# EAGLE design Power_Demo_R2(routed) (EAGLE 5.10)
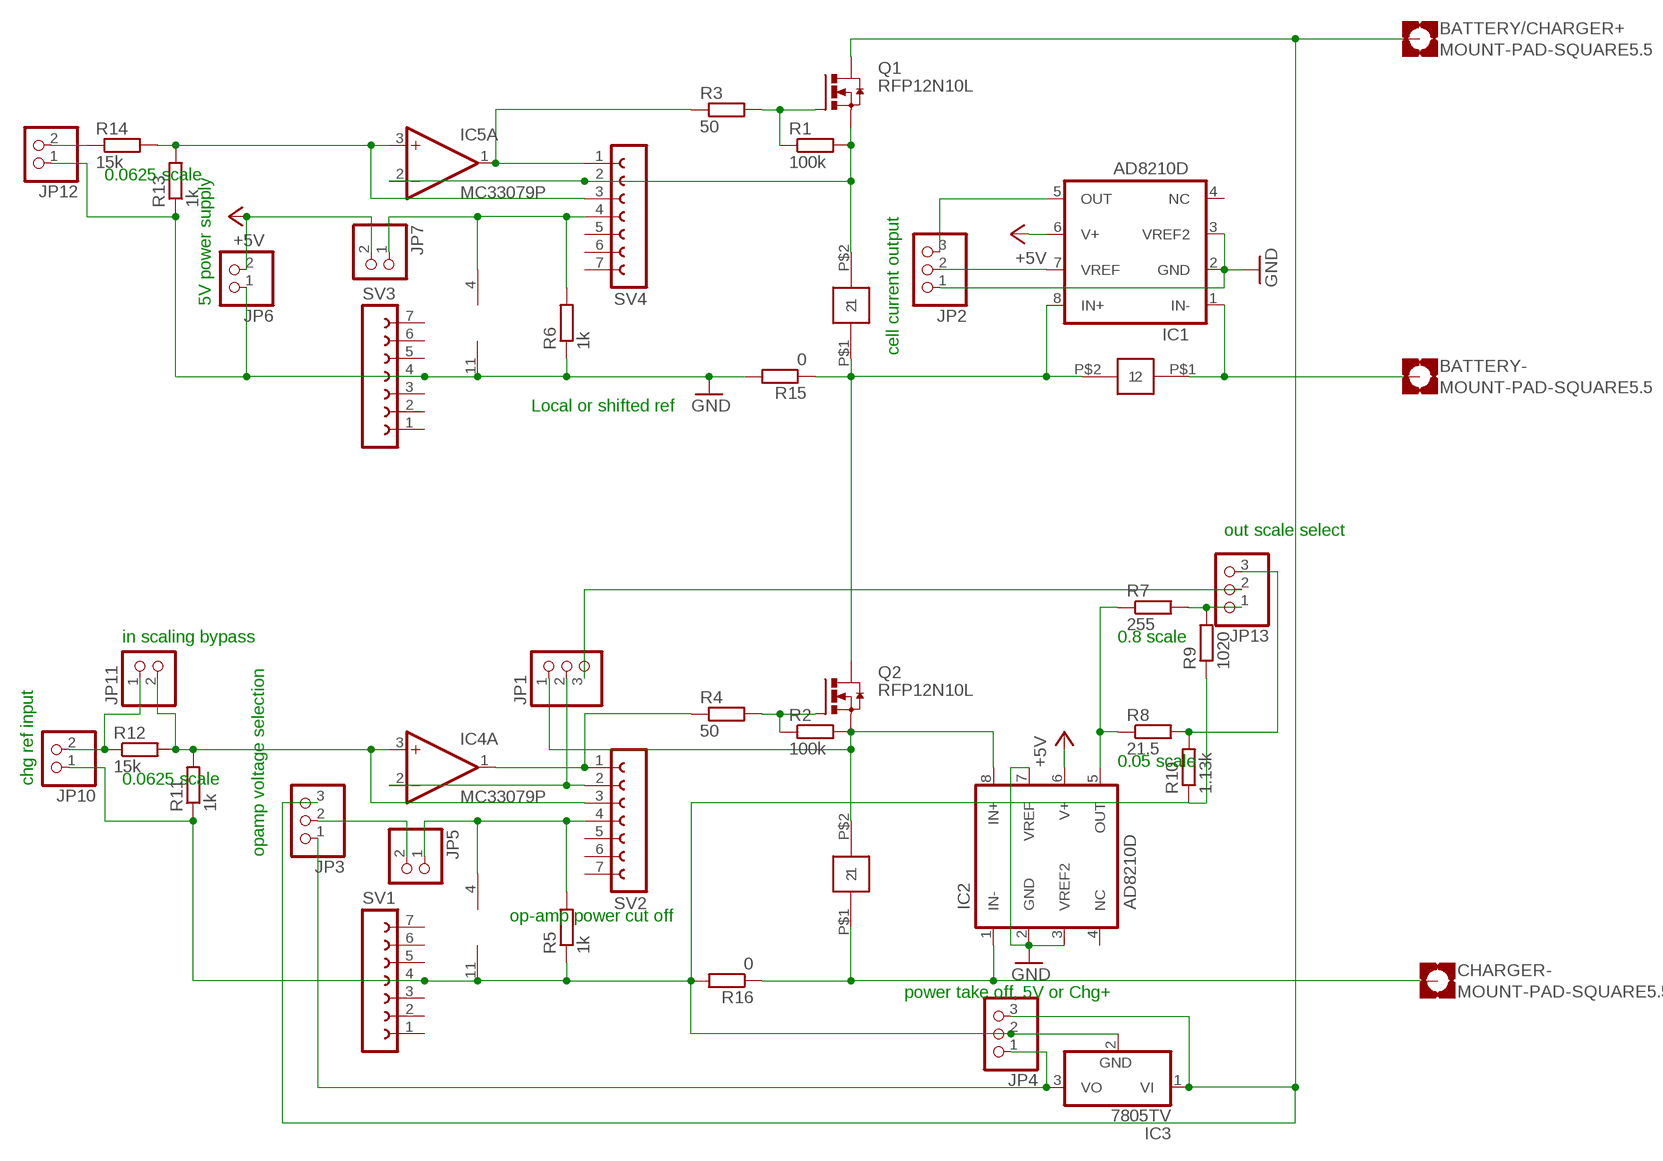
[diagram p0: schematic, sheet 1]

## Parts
BATTERY-  MOUNT-PAD-SQUARE5.5  [5,5-PAD-SQUARE]
BATTERY/CHARGER+  MOUNT-PAD-SQUARE5.5  [5,5-PAD-SQUARE]
CHARGER-  MOUNT-PAD-SQUARE5.5  [5,5-PAD-SQUARE]
IC1  AD8210D  [SO08]
IC2  AD8210D  [SO08]
IC3  7805TV  [TO220V]
IC4  MC33079P  [DIL14]
IC5  MC33079P  [DIL14]
JP1  PINHD-1X3  [1X03]
JP2  PINHD-1X3  [1X03]
JP3  PINHD-1X3  [1X03]
JP4  PINHD-1X3  [1X03]
JP5  PINHD-1X2  [1X02]
JP6  PINHD-1X2  [1X02]
JP7  PINHD-1X2  [1X02]
JP10  PINHD-1X2  [1X02]
JP11  PINHD-1X2  [1X02]
JP12  PINHD-1X2  [1X02]
JP13  PINHD-1X3  [1X03]
Q1  RFP12N10L  [TO220-W/657-20ABP]
Q2  RFP12N10L  [TO220-W/657-20ABP]
R1  100k  R-EU_R0805  [R0805]
R2  100k  R-EU_R0805  [R0805]
R3  50  R-EU_R0805  [R0805]
R4  50  R-EU_R0805  [R0805]
R5  1k  R-EU_R0805  [R0805]
R6  1k  R-EU_R0805  [R0805]
R7  255  R-EU_R0805  [R0805]
R8  21.5  R-EU_R0805  [R0805]
R9  1020  R-EU_R0805  [R0805]
R10  1.13k  R-EU_R0805  [R0805]
R11  1k  R-EU_R0805  [R0805]
R12  15k  R-EU_R0805  [R0805]
R13  1k  R-EU_R0805  [R0805]
R14  15k  R-EU_R0805  [R0805]
R15  0  R-EU_R0805  [R0805]
R16  0  R-EU_R0805  [R0805]
SV1  FE07-1  [FE07]
SV2  FE07-1  [FE07]
SV3  FE07-1  [FE07]
SV4  FE07-1  [FE07]
U$1  630HR050E  [630HR050E]
U$2  630HR050E  [630HR050E]
U$3  630HR050E  [630HR050E]

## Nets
+5V: IC1.6(V+) IC2.6(V+) JP6.2 JP7.2
GND: IC1.2(GND) IC1.3(VREF2) IC2.2(GND) IC2.3(VREF2) IC2.7(VREF) IC5.11(P:V-) JP2.1 JP6.1 JP12.1 R6.1 R13.1 R15.2 SV3.4
LOAD: BATTERY/CHARGER+.B5,5(MOUNT) IC3.1(VI) JP3.3 JP4.3 Q1.2(D)
N$1: IC1.8(IN+) Q2.2(D) R15.1 U$1.P$1 U$2.P$2
N$2: IC3.3(VO) JP3.1 JP4.1
N$3: IC2.8(IN+) JP1.1 Q2.3(S) R2.2 U$3.P$2
N$4: IC1.5(OUT) JP2.3
N$5: BATTERY-.B5,5(MOUNT) IC1.1(IN-) U$2.P$1
N$6: Q2.1(G) R2.1 R4.2
N$8: Q1.1(G) R1.1 R3.2
N$9: IC1.7(VREF) JP2.2
N$10: JP1.3 JP13.2
N$11: CHARGER-.B5,5(MOUNT) IC2.1(IN-) R16.1 U$3.P$1
N$12: IC4.4(P:V+) JP5.1 R5.2 SV2.4
N$13: IC4.1(A:OUT) R4.1 SV2.1
N$14: IC4.2(A:-IN) JP1.2 SV2.2
N$15: JP13.1 R7.2 R9.2
N$17: JP10.2 JP11.1 R12.1
N$18: JP3.2 JP5.2
N$19: IC4.3(A:+IN) JP11.2 R11.2 R12.2 SV2.3
N$20: IC5.1(A:OUT) R3.1 SV4.1
N$21: IC5.2(A:-IN) Q1.3(S) R1.2 SV4.2 U$1.P$2
N$22: IC2.5(OUT) R7.1 R8.1
N$23: JP13.3 R8.2 R10.2
N$24: IC5.4(P:V+) JP7.1 R6.2 SV4.4
N$27: JP12.2 R14.1
N$28: IC5.3(A:+IN) R13.2 R14.2 SV4.3
N$29: IC3.2(GND) IC4.11(P:V-) JP4.2 JP10.1 R5.1 R9.1 R10.1 R11.1 R16.2 SV1.4
Unconnected: IC4.5(B:+IN) IC4.6(B:-IN) IC4.7(B:OUT) IC4.8(C:OUT) IC4.9(C:-IN) IC4.10(C:+IN) IC4.12(D:+IN) IC4.13(D:-IN) IC4.14(D:OUT) IC5.5(B:+IN) IC5.6(B:-IN) IC5.7(B:OUT) IC5.8(C:OUT) IC5.9(C:-IN) IC5.10(C:+IN) IC5.12(D:+IN) IC5.13(D:-IN) IC5.14(D:OUT) SV1.1 SV1.2 SV1.3 SV1.5 SV1.6 SV1.7 SV2.5 SV2.6 SV2.7 SV3.1 SV3.2 SV3.3 SV3.5 SV3.6 SV3.7 SV4.5 SV4.6 SV4.7

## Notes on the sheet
- 0.0625 scale
- cell current output
- 5V power supply
- Local or shifted ref
- out scale select
- in scaling bypass | 0.8 scale
- 0.05 scale
- chg ref input | 0.0625 scale
- opamp voltage selection
- op-amp power cut off
- power take off, 5V or Chg+

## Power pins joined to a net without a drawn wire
NC: IC1.4(NC) IC2.4(NC)

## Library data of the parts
BATTERY- BATTERY/CHARGER+ CHARGER- = holes:MOUNT-PAD-SQUARE: MOUNTING PAD, square
IC1 IC2 = NEWPARTS:AD8210: High Voltage, Bidirectional Current Shunt Monitor
IC3 = linear:78*: Positive VOLTAGE REGULATOR Source: http://cache.national.com/ds/LM/LM78L05.pdf http://www.fairchildsemi.com/ds/LM/LM7805.pdf
IC4 IC5 = linear:MC33079: OP AMP
JP1-JP4 JP13 = pinhead:PINHD-1X3: PIN HEADER
JP5-JP7 JP10-JP12 = pinhead:PINHD-1X2: PIN HEADER
Q1 Q2 = NEWPARTS:RFP12N10L: N-Channel Power MOSFET 100V; 12A; 0,2Ohm< Logic Level
R1-R16 = rcl:R-EU_: RESISTOR, European symbol
SV1-SV4 = con-lsta:FE07-1: FEMALE HEADER
U$1-U$3 = NEWPARTS:630HR050E

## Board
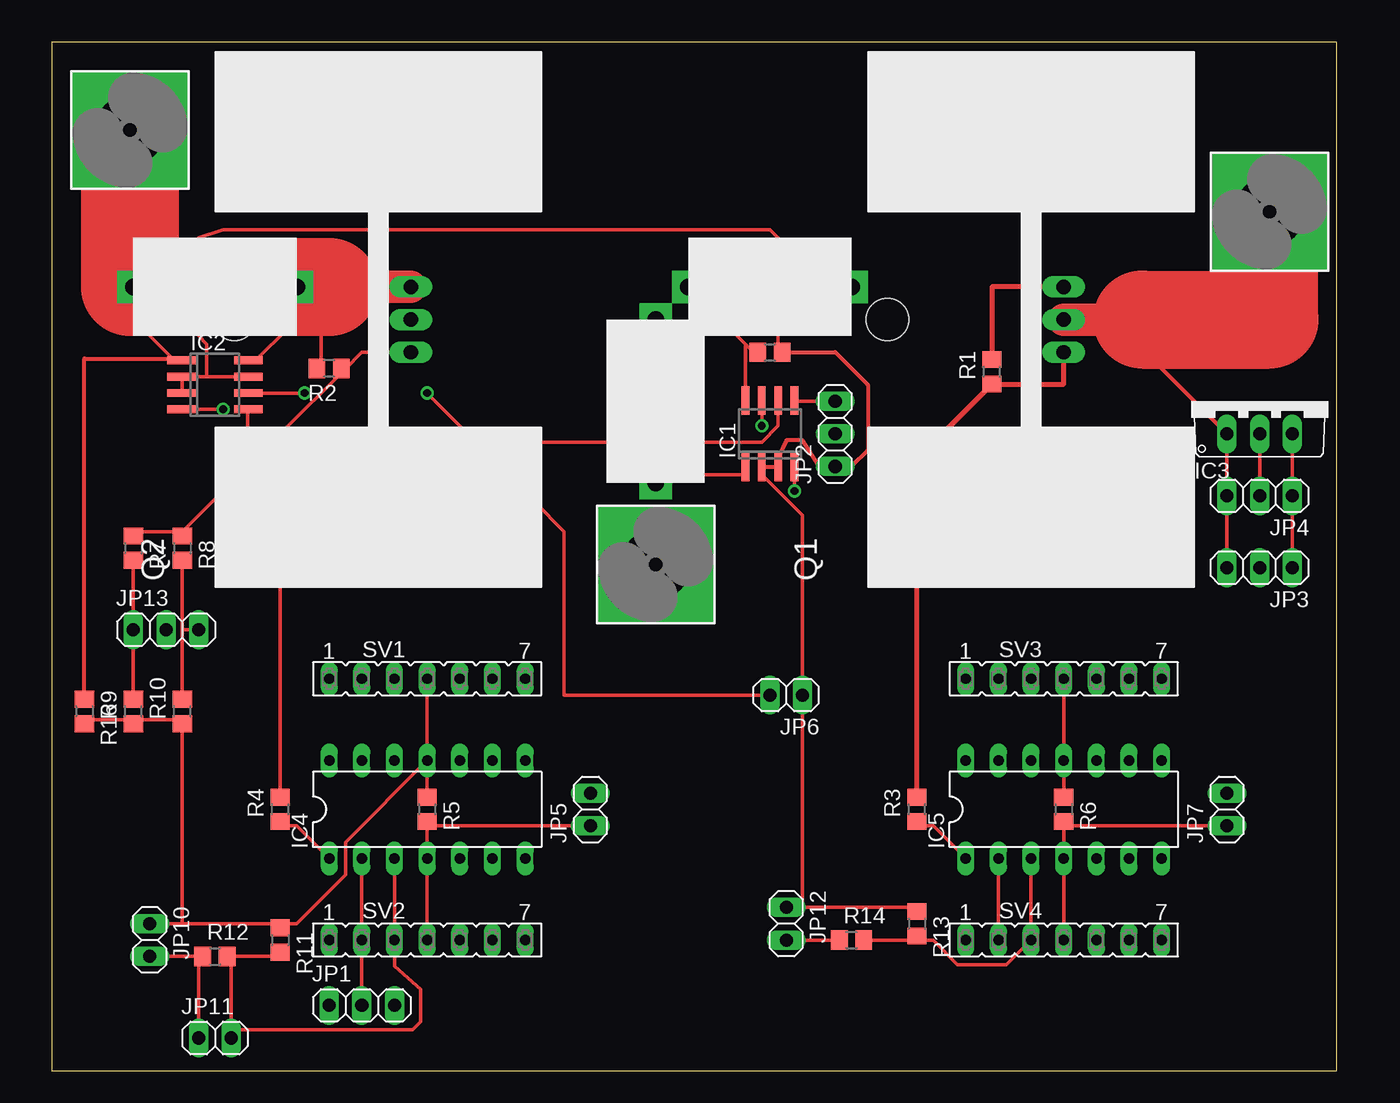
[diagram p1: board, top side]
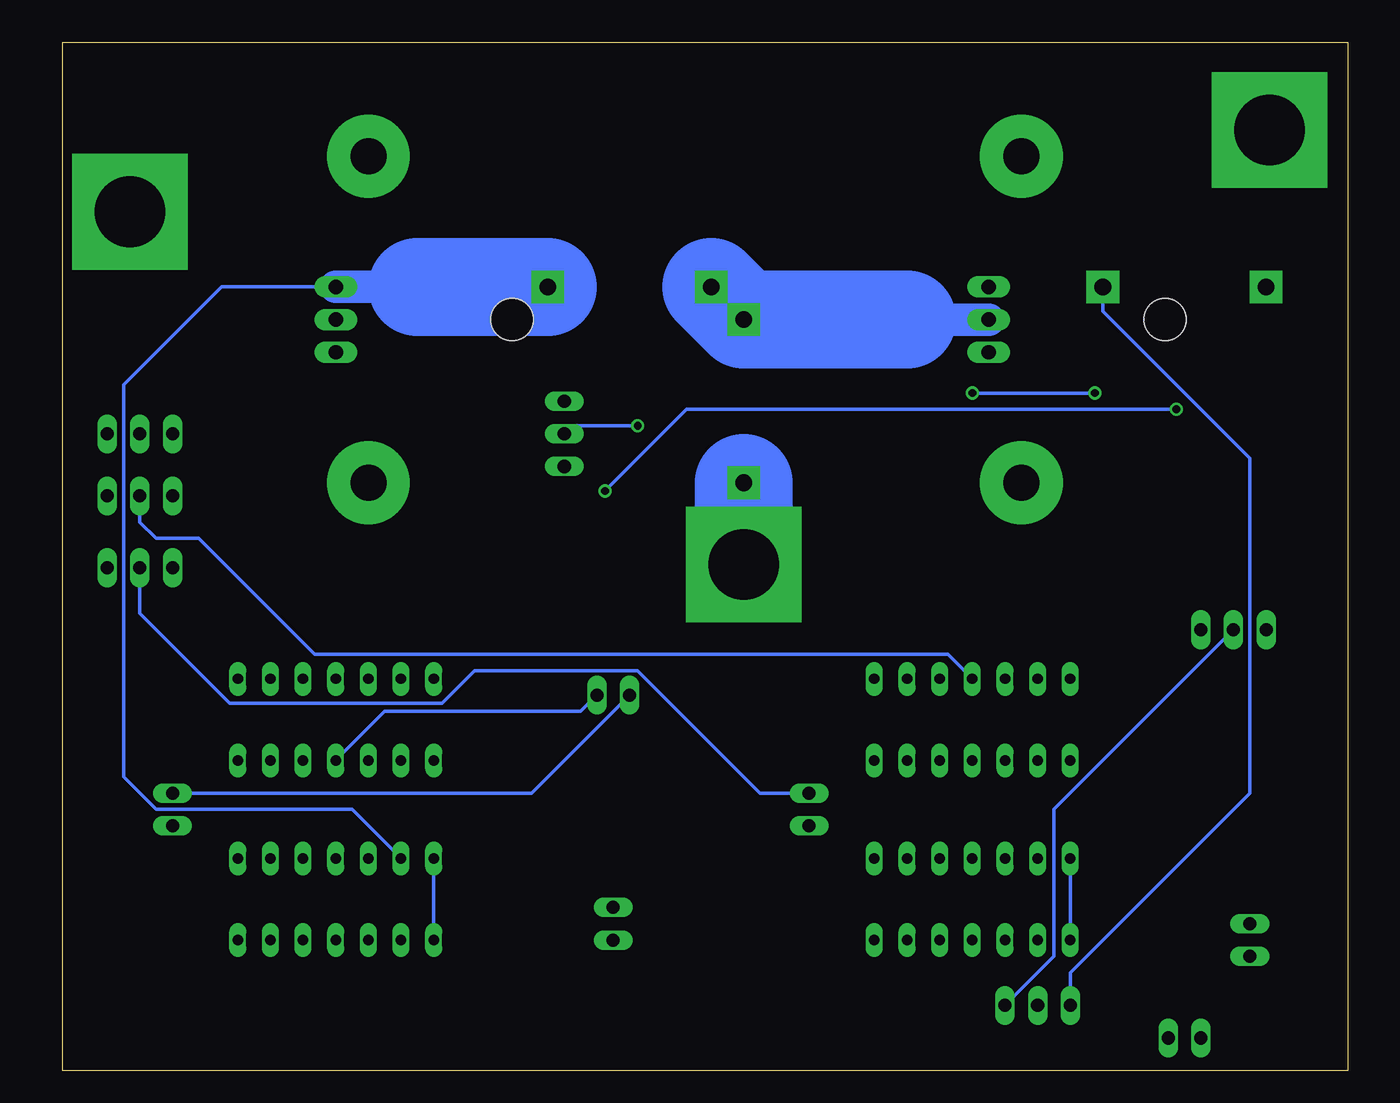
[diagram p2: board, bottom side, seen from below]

Size 100 x 80 mm. Coordinates in mm from the lower left corner, seen from the top.
Outline: 0,0 100,0 100,80 0,80 0,0
Copper layers (1*16): Top 0.035mm / dielectric 1.5mm / Bottom 0.035mm
Design rules "default": minimum track width 10mil, minimum drill 24mil, track to track 8mil, track to pad 8mil, pad to pad 8mil, via to via 8mil, smd to smd 8mil, copper to edge 40mil, drill to drill 8mil, minimum pad ring 10mil, minimum via ring 8mil, stop-mask expansion 4mil, vias tented up to drill 0mil, thermal gap 10mil

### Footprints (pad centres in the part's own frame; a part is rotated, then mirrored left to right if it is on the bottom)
5,5-PAD-SQUARE = drill 5.5 pad 9 square: B5,5 0,0
SO08 = smd 0.6 x 2.2: 1 -1.905,-2.6; 2 -0.635,-2.6; 3 0.635,-2.6; 4 1.905,-2.6; 5 1.905,2.6; 6 0.635,2.6; 7 -0.635,2.6; 8 -1.905,2.6
TO220V = drill 1.016 long: 1 -2.54,-2.54; 2 0,-2.54; 3 2.54,-2.54
DIL14 = drill 0.813 long: 1 -7.62,-3.81; 2 -5.08,-3.81; 3 -2.54,-3.81; 4 0,-3.81; 5 2.54,-3.81; 6 5.08,-3.81; 7 7.62,-3.81; 8 7.62,3.81; 9 5.08,3.81; 10 2.54,3.81; 11 0,3.81; 12 -2.54,3.81; 13 -5.08,3.81; 14 -7.62,3.81
1X03 = drill 1.016 long: 1 -2.54,0; 2 0,0; 3 2.54,0
1X02 = drill 1.016 long: 1 -1.27,0; 2 1.27,0
TO220-W/657-20ABP = drill 1.118 long: 1 -2.54,-2.54; 2 0,-2.54; 3 2.54,-2.54 | drill 2.8 pad 6.452 round: P$1 -12.7,0; P$2 12.7,0 | hole 3.302: 0,11.176
R0805 = smd 1.3 x 1.5: 1 -0.95,0; 2 0.95,0
FE07 = drill 0.813 long: 1 -7.62,0; 2 -5.08,0; 3 -2.54,0; 4 0,0; 5 2.54,0; 6 5.08,0; 7 7.62,0
630HR050E = drill 1.3 pad 2.54 square: P$1 -6.35,0; P$2 6.35,0

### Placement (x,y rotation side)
BATTERY-  46.99,39.37 0 top
BATTERY/CHARGER+  94.74,66.8 0 top
CHARGER-  6.1,73.15 0 top
IC1  55.88,49.53 0 top
IC2  12.7,53.34 270 top
IC3  93.98,52.07 0 top
IC4  29.21,20.32 0 top
IC5  78.74,20.32 0 top
JP1  24.13,5.08 0 top
JP2  60.96,49.53 90 top
JP3  93.98,39.12 180 top
JP4  93.98,44.7 180 top
JP5  41.91,20.32 90 top
JP6  57.15,29.21 180 top
JP7  91.44,20.32 90 top
JP10  7.62,10.16 270 top
JP11  12.7,2.54 0 top
JP12  57.15,11.43 270 top
JP13  8.89,34.29 0 top
Q1  76.2,58.42 90 top
Q2  25.4,58.42 90 top
R1  73.15,54.36 90 top
R2  21.59,54.61 180 top
R3  67.31,20.32 90 top
R4  17.78,20.32 90 top
R5  29.21,20.32 270 top
R6  78.74,20.32 270 top
R7  6.35,40.64 270 top
R8  10.16,40.64 270 top
R9  6.35,27.94 90 top
R10  10.16,27.94 90 top
R11  17.78,10.16 270 top
R12  12.7,8.89 0 top
R13  67.31,11.43 270 top
R14  62.23,10.16 0 top
R15  55.88,55.88 0 top
R16  2.54,27.94 270 top
SV1  29.21,30.48 0 top
SV2  29.21,10.16 0 top
SV3  78.74,30.48 0 top
SV4  78.74,10.16 0 top
U$1  55.88,60.96 0 top
U$2  46.99,52.07 90 top
U$3  12.7,60.96 0 top

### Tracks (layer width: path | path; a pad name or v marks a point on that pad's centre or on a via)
+5V  (via drill 0.61)
  Top 0.254: 33.02,48.9 39.88,41.91 39.88,29.21 JP6.2 | v29.21,52.7 33.02,48.9 | IC2.6 v19.68,52.7 | 33.02,48.9 55.24,48.9 56.52,50.16 IC1.6
  Bottom 0.254: v19.68,52.7 v29.21,52.7 | JP7.2 63.5,21.59 JP6.2
GND
  Top 0.254: R6.1 IC5.11 SV3.4 | 58.42,12.7 67.31,12.7 R13.1 | 58.42,12.7 JP6.1 58.42,43.18 55.24,46.35 IC1.2 | 58.42,12.7 JP12.1 | 10.16,53.98 10.16,52.7 IC2.3 | 10.16,53.98 12.06,53.98 | 12.06,53.98 IC2.7 | 10.16,53.98 IC2.2 | 12.06,53.98 12.06,56.52 11.43,57.15 11.43,64.77 13.34,65.41 55.88,65.41 56.52,64.77 56.52,55.88 R15.2
  Top 0.305: IC1.2 IC1.3 56.52,47.62 57.15,49.02 58.42,49.02 59.69,46.99 JP2.1 62.23,46.99 63.5,48.26 63.5,53.34 60.96,55.88 R15.2
  Bottom 0.254: IC5.11 74.93,27.94 59.69,27.94 JP6.1
LOAD
  Top 0.254: JP3.3 JP4.3 IC3.1
  Top 0.305: Q1.2 82.55,58.42 IC3.1
  Top 2.54: Q1.2 84.84,58.42
  Top 7.62: BATTERY/CHARGER+.B5,5 94.74,58.42 84.84,58.42
N$1
  Top 0.254: U$1.P$1 53.98,56.52 | 53.98,56.52 54.61,55.88 R15.1 | 53.98,56.52 IC1.8
  Bottom 2.54: Q2.2 34.29,58.42
  Bottom 7.62: U$1.P$1 U$2.P$2 34.29,58.42
N$2
  Top 0.254: JP3.1 JP4.1 IC3.3
N$3
  Top 0.254: R2.2 20.95,54.61 20.95,60.96 | IC2.8 15.88,55.24 18.41,57.78 U$3.P$2
  Top 2.54: 21.59,60.96 Q2.3
  Top 7.62: U$3.P$2 20.95,60.96 21.59,60.96
  Bottom 0.254: JP1.1 21.59,7.62 7.62,21.59 7.62,47.62 19.05,59.05 U$3.P$2
N$4
  Top 0.254: JP2.3 57.78,52.07 IC1.5
N$5
  Top 0.254: U$2.P$1 47.62,46.35 53.98,46.35 IC1.1
  Bottom 7.62: BATTERY-.B5,5 U$2.P$1
N$6
  Top 0.254: 22.86,54.61 17.78,49.53 R4.2 | Q2.1 24.13,55.88 22.86,54.61 | 22.86,54.61 R2.1
N$8
  Top 0.406: Q1.1 78.74,53.41 R1.1 67.31,47.56 R3.2
N$9  (via drill 0.61)
  Top 0.254: v55.24,50.16 IC1.7
  Bottom 0.254: v55.24,50.16 60.33,50.16 JP2.2
N$10
  Bottom 0.254: JP1.3 22.86,8.89 22.86,20.32 JP13.2
N$11
  Top 0.254: IC2.1 9.53,55.24 9.4,55.37 6.99,57.78 U$3.P$1
  Top 0.305: R16.1 2.54,55.37 9.4,55.37
  Top 7.62: CHARGER-.B5,5 6.1,60.96 U$3.P$1
N$12
  Top 0.254: 29.21,19.05 IC4.4 SV2.4 | 29.21,19.05 JP5.1 | 29.21,19.05 R5.2
N$13
  Top 0.254: IC4.1 19.05,19.05 17.78,19.05 R4.1
  Bottom 0.254: SV2.1 IC4.1
N$14
  Top 0.254: JP1.2 SV2.2 IC4.2
N$15
  Top 0.254: R9.2 JP13.1 R7.2
N$17
  Top 0.254: 11.43,8.89 JP10.2 | JP11.1 11.43,8.89 | 11.43,8.89 R12.1
N$18
  Bottom 0.254: JP5.2 45.72,21.59 55.24,31.11 67.94,31.11 70.48,28.57 87,28.57 93.98,35.56 JP3.2
N$19
  Top 0.254: IC4.3 SV2.3 26.67,8.13 28.7,6.35 28.7,3.81 28.07,3.17 13.97,3.17 | 13.97,8.89 17.78,8.89 R11.2 | 13.97,3.17 13.97,8.89 | 13.97,8.89 R12.2 | JP11.2 13.97,3.17
N$20
  Top 0.254: IC5.1 68.58,19.05 67.31,19.05 R3.1
  Bottom 0.254: SV4.1 IC5.1
N$21
  Top 0.254: SV4.2 IC5.2
  Top 0.406: R1.2 73.15,60.96 Q1.3
  Bottom 0.254: IC5.2 77.47,20.32 92.71,20.32 95.25,22.86 95.25,53.34 87.63,60.96 Q1.3
  Bottom 2.54: Q1.3 72.39,60.96
  Bottom 7.62: 72.39,60.96 U$1.P$2
N$22
  Top 0.254: 10.16,41.91 6.35,41.91 R7.1 | 10.16,41.91 15.24,46.99 15.24,51.44 IC2.5 | 10.16,41.91 R8.1
N$23
  Top 0.254: R10.2 10.16,34.29 | 10.16,34.29 R8.2 | 10.16,34.29 JP13.3
N$24
  Top 0.254: 78.74,19.05 IC5.4 SV4.4 | 78.74,19.05 JP7.1 | 78.74,19.05 R6.2
N$27
  Top 0.254: JP12.2 R14.1
N$28
  Top 0.254: R14.2 67.31,10.16 | IC5.3 SV4.3 74.3,8.26 70.48,8.26 68.58,10.16 67.31,10.16 | 67.31,10.16 R13.2
N$29
  Top 0.254: 6.35,27.3 2.54,27.3 R16.2 | 6.35,27.3 10.16,27.3 R10.1 10.16,11.43 | 6.35,27.3 R9.1 | JP10.1 10.16,11.43 | 10.16,11.43 17.78,11.43 | JP4.2 IC3.2 | IC4.11 R5.1 | IC4.11 SV1.4 | 17.78,11.43 19.05,11.43 22.86,15.24 22.86,17.78 IC4.11 | 17.78,11.43 R11.1
  Bottom 0.254: JP4.2 93.98,42.67 92.71,41.4 89.41,41.4 80.39,32.38 31.11,32.38 SV1.4
NC  (via drill 0.61)
  Top 0.254: IC2.4 v13.34,51.44 | v57.78,45.09 IC1.4
  Bottom 0.254: v13.34,51.44 51.44,51.44 v57.78,45.09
